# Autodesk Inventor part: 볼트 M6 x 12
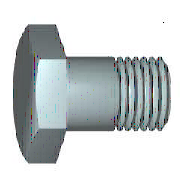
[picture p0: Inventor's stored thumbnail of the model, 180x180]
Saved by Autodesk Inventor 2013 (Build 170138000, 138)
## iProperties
IsCustomPart: 0
Created: 2012-02
Part Number: 볼트 M6 x 12
Material: 스테인리스강
Description: 6각 머리 나사. 제품 등급 C
Document SubType Name: Modeling
Standard: ISO 4018
Designer: mduedu
Standard Revision: Third edition 1999-08-15
Standards Organization: ISO
Language: ko-KR
Size Designation: M6 x 12
Categories: <MemberInstance><Categories><Category DisplayName="조임쇠" InternalName="e4da775c-781d-43d5-af7c-5136215cf5a6" Mnemonic="FSTN"><Category DisplayName="볼트" InternalN
Density: 8.08 g/cm^3
Mass: 5.5158 g
Surface Area: 5.26064 cm^2
Volume: 0.682649 cm^3
Author: mduedu
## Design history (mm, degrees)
node "WorkPlane1"
node "WorkPoint1"
node "MSC_A1"
node "MSC_PF1"
node "MSC_PT1"
body "Solid1"
node "스케치1"
sketch "스케치2"
  geometry: L1 (-5, 2.887)-(-5, -2.887); L2 (0, 5.773)-(-5, 2.887); L3 (5, 2.887)-(0, 5.773); L4 (5, -2.887)-(5, 2.887); L5 (0, -5.773)-(5, -2.887); L6 (-5, -2.887)-(0, -5.773); C1 r 5 at (0, 0); 1 further point
  constraints: 12 end point, 6 tangent, 2 parallel, 2 vertical, 1 centre point
  dimensions: "d1" = 10 diameter of C1 (= ParS); "d29" = 0 distance of point (0, 0) C1.centre; "d30" = 0 distance of C1.centre point (0, 0)
extrude "돌출1" new body sketch "스케치2" distance "d6" = 4 (= ParK); taper "d7" = 0 deg
revolve "회전1" stored, may be unused: angle "d14" = 360 deg
revolve "회전2" stored, may be unused: angle "d21" = 360 deg
chamfer "모따기1" distance "d22" = 0.5 (= 0.5 x PTC); stored, may be unused: second distance "d23" = 0.5 (= 0.5 x PTC), angle "d39" = 45 deg
fillet "모깎기1" dims "d24" = 0.25 (= r)
feature "스레드1" dims "d32" = 0, "b" = 10.5 (= NLG - 1.5 x PTC)
sketch "스케치3"
  geometry: L1 (5, 4)-(5.873, 4); L2 (5.873, 3.496)-(5, 4); L3 (5.873, 4)-(5.873, 3.496); L4 (0, -0.8)-(0, 4.8) reference; L5 (5.773, 0)-(5.773, 4) reference
  constraints: 6 end point, 1 horizontal, 1 vertical
  dimensions: "d25" = 0.1 distance between parallel lines of L5 L3; "d26" = 0 distance from line of L5.end L1; "d27" = 60 deg angle of L3 L2; "d28" = 5 distance from line of L4 L1.start (= 0.5 x ParS)
sketch "스케치4"
  geometry: L1 (0, -12)-(0, 0); L2 (-3, -12)-(0, -12); L3 (-3, 0)-(-3, -12); L4 (0, 0)-(-3, 0); L5 (0, -12)-(0, 0); L6 (-3.6, 0)-(0.6, 0) reference; L7 (0, -14.4)-(0, 2.4) reference
  constraints: 10 end point, 2 horizontal, 2 vertical
  dimensions: "d18" = 3 distance of L1.start L2.start (= 0.5 x NND); "d20" = 12 distance of L3.start L2.start (= NLG); "d33" = 0 distance between parallel lines of L7 L1; "d34" = 0 distance between parallel lines of L6 L4
other parameters: "NND" = 6 [user parameter; used in 2 equation terms], "NLG" = 12 [user parameter; used in 2 equation terms], "PTC" = 1 [user parameter; used in 3 equation terms], "ParK" = 4 [user parameter; used in 1 equation term], "ParS" = 10 [user parameter; used in 3 equation terms], "msp_es" = 5.77367 (= 0.577367 x ParS) [user parameter], "r" = 0.25 [user parameter; used in 1 equation term], "d2" = 15 (derived), "d4" = 17.32102 (derived), "d8" = 15 (derived), "d10" = 0 (derived), "d12" = 30 deg (derived), "d15" = 0 (derived), "d37" = 0, "d38" = 0, "d40" = 0, "d41" = 0, "d42" = 0, "THREADDIA" = 6 (= NND) [user parameter]
